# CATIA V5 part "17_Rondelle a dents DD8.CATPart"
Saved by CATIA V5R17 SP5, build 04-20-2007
Part number: 17_Rondelle a dents DD8
Revision: ANY
Definition: Rondelle à dents DD8
Source: Unknown
Bounding box of the stored display mesh (mm): x -0.8 to 0.8, y -7.079 to 7.079, z -7.086 to 7.039
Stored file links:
  C:\Users\Frédéric\Documents\WF\STSCPI 09-11\Projets\Projet multiplicateur eolienne\Maquette eolienne\17_Rondelle a dents DD8.CATPart
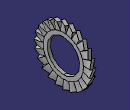
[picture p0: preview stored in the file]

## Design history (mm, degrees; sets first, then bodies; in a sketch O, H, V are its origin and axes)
AxisSystem1: origin (0, 0, 0), X (1, 0, 0), Y (0, 1, 0), Z (0, 0, 1)
Set1
  Plane1: type OffsetPt, RefPlane YZ plane of AxisSystem1, RefPoint vertex [face of Solid1 | face of Solid1 | face of Solid1]
  Plane2: type OffsetPt, RefPlane YZ plane of AxisSystem1, RefPoint vertex [face of Solid1 | face of Solid1 | face of Solid1]
Body1 "NONE" (main body)
  Solid1 "Manifold Solid #4507": solid without history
